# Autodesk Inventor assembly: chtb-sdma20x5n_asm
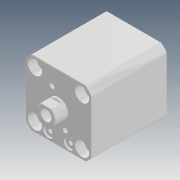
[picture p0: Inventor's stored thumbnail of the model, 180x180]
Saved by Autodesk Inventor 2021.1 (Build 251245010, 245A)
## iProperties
Created: 2018-05
Part Number: chtb-sdma20x5n_asm
Description: STEP AP214
Document SubType Name: Assembly
Designer: user
Title: chtb-sdma20x5n_asm.STEP
Revision Number: ÈÎºÎ
Sending System: SolidWorks 2016
Preprocessor: SwSTEP 2.0
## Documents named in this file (5)
- D:\Vault_2016\Projekty\Clamptek\Hydraulic\CHTB\CHTB-20\Inventor\CHTB-SDMA20x5N\chtb-sdma20x5n_asm.iam
- D:\Vault_2016\Projekty\Clamptek\Hydraulic\CHTB\CHTB-20\Inventor\CHTB-SDMA20x5N\CHTB-SDMA20X5NBT.ipt
- D:\Vault_2016\Projekty\Clamptek\Hydraulic\CHTB\CHTB-20\Inventor\CHTB-SDMA20x5N\CHTB-SDMA20X5NHSG.ipt
- D:\Vault_2016\Projekty\Clamptek\Hydraulic\CHTB\CHTB-20\Inventor\CHTB-SDMA20x5N\QG_3.ipt
- D:\Vault_2016\Projekty\Clamptek\Hydraulic\CHTB\CHTB-20\Inventor\CHTB-SDMA20x5N\socket set screw flat point_iso_ISO 4026 - M5 x 5-N.ipt
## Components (5 placed, 5 different names)
1. CHTB-SDMA20X5NBT_1
2. CHTB-SDMA20X5NHSG_2
3. QG_3_3
4. socket set screw flat point_iso_ISO 4026 - M5 x 5-N_4
5. socket set screw flat point_iso_ISO 4026 - M5 x 5-N_5
